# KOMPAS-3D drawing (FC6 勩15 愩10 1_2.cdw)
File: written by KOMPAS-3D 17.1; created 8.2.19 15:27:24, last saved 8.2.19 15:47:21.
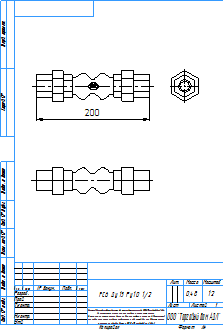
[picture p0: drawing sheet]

Sheet 1: A4, portrait

Title block, sheet 1: name: FC6 Ду15 Ру10 1/2; mass: 0,48; sheets: 1; sheet format: A4; stored path: \\adlc.lan\data\АДЛ_ПКД\3D-модели\ADL production\Гибкие вставки серии FC\FC6\KOMPAS 2D\FC6 Ду15 Ру10 1_2.cdw

Views: Вид 1
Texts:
  kka
  adl
  Рама для чертежей
  Лит-Масса-Масштаб
  Материал-Предприятие
  Масштаб
  Изм.
  Лист
  № докум.
  Подп.
  Дата
  Лит.
  Разраб.
  Пров.
  Т.контр.
  Листов
  Внимание! Данный продукт является объектом авторского права ООО «Торговый Дом АДЛ».
  Запрещается изменение, копирование, распространение
  (в том числе путем копирования на другие сайты и ресурсы в Интернете)
  или любое иное использование информации и объектов без предварительного
  согласия правообладателя (ООО «Торговый Дом АДЛ»).
  Н.контр.
  Утв.
  ООО "Торговый дом АДЛ"
  Изменение
  Номер документа
  Подпись
  Обозначение документа
  Наименование изделия
  Масса изделия по ГОСТ 2.109-73
  Порядковый номер листа
  Общее количество листов в документе
  Характер работы, выполненной лицом, подписавшим документ
  Наименование или индекс предприятия, выпускающего документ
  Инв. № подл.
  Подп. и дата
  Взам. инв. №
  Инв. № дубл.
  Инвентарный номер подлинника по ГОСТ 2.501-68
  Подпись принявшего подлинник в отдел технической документации
  Инвентарный номер подлинника, взамен которого выпущен данный подлинник
  Инвентарный номер дубликата по ГОСТ 2.502-68
  Подпись принявшего дубликат в отдел технической документации
  Справ. №
  Перв. примен.
  Обозначение документа, взамен или на основании которого выпущен данный документ
  Обозначение документа, в котором впервые записан данный документ
  Подпись лица, копировавшего чертеж
  Обозначение формата листа
  !Рама для чертежа
Dimensions and other numbers on the sheet: 200; 1:2; 1; 0,48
